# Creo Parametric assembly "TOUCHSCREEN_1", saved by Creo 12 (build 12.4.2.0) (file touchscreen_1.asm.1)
Units: Custom; MM, KILOGRAM, SECS

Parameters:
  PTC_WM_ITERATION = "0"
  PTC_WM_VERSION = "-.0"
  PTC_WM_LIFECYCLE_STATE = "In Work"
  PTC_WM_LIFECYCLE = "MO_CADDocument"
  PTC_WM_CREATED_BY = "Maximilian Roepper (Z0017RMS: MO)"
  PTC_WM_CREATED_ON = "18-Sep-26 11:36:42 AM"
  PTC_WM_MODIFIED_BY = "Maximilian Roepper (Z0017RMS: MO)"
  PTC_WM_MODIFIED_ON = "18-Sep-26 11:36:46 AM"
  PDMLINKNUMBER = "PDM000071455223"
  PTC_WM_NUMBER = "PDM000071455223"

Other parameters: WEIGHT, WEIGHT_FACTOR, WEIGHT_ADD, MC_ERRORS, SUPPLIER

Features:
  1. coordinate system
  2. imported feature
  3. component "TOUCH_ROUTS_1"
  4. component "TOUCH_PROTECT_1"
  5. component "TOUCH_CABLE_1"

Other named items: DRW_VIEW_ORG, ROUGH-GROB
